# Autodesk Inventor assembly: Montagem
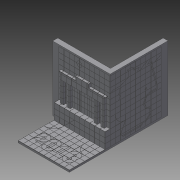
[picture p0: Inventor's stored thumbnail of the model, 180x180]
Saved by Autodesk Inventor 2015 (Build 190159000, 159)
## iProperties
Created: 2015-04
Part Number: Montagem
Document SubType Name: Assembly
Designer: Felipe
Author: Felipe
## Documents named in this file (65)
- F:\Visitor Experience Project\WSI2015 - Visitor Experience Project\#12- Wall and Floor Tiling\01 - 3D Models\Inventor Files\Montagem.iam
- C:\Users\TREINA5\Documents\Inventor\CNC Turning\Azulejo (1).ipt
- C:\Users\TREINA5\Documents\Inventor\CNC Turning\Azulejo (9).ipt
- C:\Users\TREINA5\Documents\Inventor\CNC Turning\Azulejo (10).ipt
- C:\Users\TREINA5\Documents\Inventor\CNC Turning\Azulejo (3).ipt
- C:\Users\TREINA5\Documents\Inventor\CNC Turning\Azulejo (2).ipt
- C:\Users\TREINA5\Documents\Inventor\CNC Turning\Azulejo (4).ipt
- C:\Users\TREINA5\Documents\Inventor\CNC Turning\Azulejo (5).ipt
- C:\Users\TREINA5\Documents\Inventor\CNC Turning\Azulejo (7).ipt
- C:\Users\TREINA5\Documents\Inventor\CNC Turning\Azulejo (6).ipt
- C:\Users\TREINA5\Documents\Inventor\CNC Turning\Azulejo (8).ipt
- F:\Visitor Experience Project\WSI2015 - Visitor Experience Project\#12- Wall and Floor Tiling\01 - 3D Models\Inventor Files\Azulejo (11).ipt
- F:\Visitor Experience Project\WSI2015 - Visitor Experience Project\#12- Wall and Floor Tiling\01 - 3D Models\Inventor Files\Azulejo (12).ipt
- F:\Visitor Experience Project\WSI2015 - Visitor Experience Project\#12- Wall and Floor Tiling\01 - 3D Models\Inventor Files\Azulejo (13).ipt
- F:\Visitor Experience Project\WSI2015 - Visitor Experience Project\#12- Wall and Floor Tiling\01 - 3D Models\Inventor Files\Azulejo (14).ipt
- F:\Visitor Experience Project\WSI2015 - Visitor Experience Project\#12- Wall and Floor Tiling\01 - 3D Models\Inventor Files\Azulejo (15).ipt
- F:\Visitor Experience Project\WSI2015 - Visitor Experience Project\#12- Wall and Floor Tiling\01 - 3D Models\Inventor Files\Azulejo (16).ipt
- F:\Visitor Experience Project\WSI2015 - Visitor Experience Project\#12- Wall and Floor Tiling\01 - 3D Models\Inventor Files\Azulejo (17).ipt
- F:\Visitor Experience Project\WSI2015 - Visitor Experience Project\#12- Wall and Floor Tiling\01 - 3D Models\Inventor Files\Azulejo (18).ipt
- F:\Visitor Experience Project\WSI2015 - Visitor Experience Project\#12- Wall and Floor Tiling\01 - 3D Models\Inventor Files\Azulejo (19).ipt
- F:\Visitor Experience Project\WSI2015 - Visitor Experience Project\#12- Wall and Floor Tiling\01 - 3D Models\Inventor Files\Azulejo (20).ipt
- F:\Visitor Experience Project\WSI2015 - Visitor Experience Project\#12- Wall and Floor Tiling\01 - 3D Models\Inventor Files\Azulejo (21).ipt
- F:\Visitor Experience Project\WSI2015 - Visitor Experience Project\#12- Wall and Floor Tiling\01 - 3D Models\Inventor Files\Azulejo (22).ipt
- F:\Visitor Experience Project\WSI2015 - Visitor Experience Project\#12- Wall and Floor Tiling\01 - 3D Models\Inventor Files\Azulejo (23).ipt
- F:\Visitor Experience Project\WSI2015 - Visitor Experience Project\#12- Wall and Floor Tiling\01 - 3D Models\Inventor Files\Azulejo (24).ipt
- F:\Visitor Experience Project\WSI2015 - Visitor Experience Project\#12- Wall and Floor Tiling\01 - 3D Models\Inventor Files\Azulejo (25).ipt
- F:\Visitor Experience Project\WSI2015 - Visitor Experience Project\#12- Wall and Floor Tiling\01 - 3D Models\Inventor Files\Azulejo (26).ipt
- F:\Visitor Experience Project\WSI2015 - Visitor Experience Project\#12- Wall and Floor Tiling\01 - 3D Models\Inventor Files\Azulejo (27).ipt
- F:\Visitor Experience Project\WSI2015 - Visitor Experience Project\#12- Wall and Floor Tiling\01 - 3D Models\Inventor Files\Azulejo (28).ipt
- F:\Visitor Experience Project\WSI2015 - Visitor Experience Project\#12- Wall and Floor Tiling\01 - 3D Models\Inventor Files\Azulejo (29).ipt
- F:\Visitor Experience Project\WSI2015 - Visitor Experience Project\#12- Wall and Floor Tiling\01 - 3D Models\Inventor Files\Azulejo (30).ipt
- F:\Visitor Experience Project\WSI2015 - Visitor Experience Project\#12- Wall and Floor Tiling\01 - 3D Models\Inventor Files\Azulejo (31).ipt
- F:\Visitor Experience Project\WSI2015 - Visitor Experience Project\#12- Wall and Floor Tiling\01 - 3D Models\Inventor Files\Azulejo (32).ipt
- F:\Visitor Experience Project\WSI2015 - Visitor Experience Project\#12- Wall and Floor Tiling\01 - 3D Models\Inventor Files\Azulejo (33).ipt
- F:\Visitor Experience Project\WSI2015 - Visitor Experience Project\#12- Wall and Floor Tiling\01 - 3D Models\Inventor Files\Azulejo (34).ipt
- F:\Visitor Experience Project\WSI2015 - Visitor Experience Project\#12- Wall and Floor Tiling\01 - 3D Models\Inventor Files\Azulejo (35).ipt
- F:\Visitor Experience Project\WSI2015 - Visitor Experience Project\#12- Wall and Floor Tiling\01 - 3D Models\Inventor Files\Azulejo (36).ipt
- F:\Visitor Experience Project\WSI2015 - Visitor Experience Project\#12- Wall and Floor Tiling\01 - 3D Models\Inventor Files\Azulejo (37).ipt
- F:\Visitor Experience Project\WSI2015 - Visitor Experience Project\#12- Wall and Floor Tiling\01 - 3D Models\Inventor Files\Azulejo (38).ipt
- F:\Visitor Experience Project\WSI2015 - Visitor Experience Project\#12- Wall and Floor Tiling\01 - 3D Models\Inventor Files\Azulejo (39).ipt
- F:\Visitor Experience Project\WSI2015 - Visitor Experience Project\#12- Wall and Floor Tiling\01 - 3D Models\Inventor Files\Azulejo (40).ipt
- F:\Visitor Experience Project\WSI2015 - Visitor Experience Project\#12- Wall and Floor Tiling\01 - 3D Models\Inventor Files\Azulejo (41).ipt
- F:\Visitor Experience Project\WSI2015 - Visitor Experience Project\#12- Wall and Floor Tiling\01 - 3D Models\Inventor Files\Azulejo (42).ipt
- F:\Visitor Experience Project\WSI2015 - Visitor Experience Project\#12- Wall and Floor Tiling\01 - 3D Models\Inventor Files\Azulejo (43).ipt
- F:\Visitor Experience Project\WSI2015 - Visitor Experience Project\#12- Wall and Floor Tiling\01 - 3D Models\Inventor Files\Azulejo (44).ipt
- F:\Visitor Experience Project\WSI2015 - Visitor Experience Project\#12- Wall and Floor Tiling\01 - 3D Models\Inventor Files\Azulejo (53).ipt
- F:\Visitor Experience Project\WSI2015 - Visitor Experience Project\#12- Wall and Floor Tiling\01 - 3D Models\Inventor Files\Azulejo (52).ipt
- F:\Visitor Experience Project\WSI2015 - Visitor Experience Project\#12- Wall and Floor Tiling\01 - 3D Models\Inventor Files\Azulejo (51).ipt
- F:\Visitor Experience Project\WSI2015 - Visitor Experience Project\#12- Wall and Floor Tiling\01 - 3D Models\Inventor Files\Azulejo (54).ipt
- F:\Visitor Experience Project\WSI2015 - Visitor Experience Project\#12- Wall and Floor Tiling\01 - 3D Models\Inventor Files\Azulejo (55).ipt
- F:\Visitor Experience Project\WSI2015 - Visitor Experience Project\#12- Wall and Floor Tiling\01 - 3D Models\Inventor Files\Azulejo (56).ipt
- F:\Visitor Experience Project\WSI2015 - Visitor Experience Project\#12- Wall and Floor Tiling\01 - 3D Models\Inventor Files\Azulejo (49).ipt
- F:\Visitor Experience Project\WSI2015 - Visitor Experience Project\#12- Wall and Floor Tiling\01 - 3D Models\Inventor Files\Azulejo (45).ipt
- F:\Visitor Experience Project\WSI2015 - Visitor Experience Project\#12- Wall and Floor Tiling\01 - 3D Models\Inventor Files\Azulejo (57).ipt
- F:\Visitor Experience Project\WSI2015 - Visitor Experience Project\#12- Wall and Floor Tiling\01 - 3D Models\Inventor Files\Azulejo (48).ipt
- F:\Visitor Experience Project\WSI2015 - Visitor Experience Project\#12- Wall and Floor Tiling\01 - 3D Models\Inventor Files\Azulejo (47).ipt
- F:\Visitor Experience Project\WSI2015 - Visitor Experience Project\#12- Wall and Floor Tiling\01 - 3D Models\Inventor Files\Azulejo (46).ipt
- F:\Visitor Experience Project\WSI2015 - Visitor Experience Project\#12- Wall and Floor Tiling\01 - 3D Models\Inventor Files\Azulejo (50).ipt
- F:\Visitor Experience Project\WSI2015 - Visitor Experience Project\#12- Wall and Floor Tiling\01 - 3D Models\Inventor Files\Azulejo (58).ipt
- F:\Visitor Experience Project\WSI2015 - Visitor Experience Project\#12- Wall and Floor Tiling\01 - 3D Models\Inventor Files\Azulejo (61).ipt
- F:\Visitor Experience Project\WSI2015 - Visitor Experience Project\#12- Wall and Floor Tiling\01 - 3D Models\Inventor Files\Azulejo (60).ipt
- F:\Visitor Experience Project\WSI2015 - Visitor Experience Project\#12- Wall and Floor Tiling\01 - 3D Models\Inventor Files\Azulejo (59).ipt
- F:\Visitor Experience Project\WSI2015 - Visitor Experience Project\#12- Wall and Floor Tiling\01 - 3D Models\Inventor Files\Azulejo (62).ipt
- F:\Visitor Experience Project\WSI2015 - Visitor Experience Project\#12- Wall and Floor Tiling\01 - 3D Models\Inventor Files\Azulejo (63).ipt
- F:\Visitor Experience Project\WSI2015 - Visitor Experience Project\#12- Wall and Floor Tiling\01 - 3D Models\Inventor Files\Parede.ipt
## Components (416 placed, 64 different names)
1. Parede:1 — Mate:1, Flush:1, Mate:2, Mate:3, Flush:2, Mate:5, Flush:3, Mate:7, Flush:4, Mate:9, Flush:5, Mate:11, Flush:6, Mate:13, Flush:7, Mate:15, Mate:17, Mate:19, Mate:21, Mate:23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
2. Azulejo (1):1 — Mate:1, Flush:1, Mate:2, Mate:4, Mate:47, Mate:197
3. Azulejo (1):2 — Mate:3, Flush:2, Mate:4, Mate:6, Mate:53
4. Azulejo (1):3 — Mate:5, Flush:3, Mate:6, Mate:8
5. Azulejo (1):4 — Mate:7, Flush:4, Mate:8, Mate:10
6. Azulejo (1):5 — Mate:9, Flush:5, Mate:10, Mate:12, Mate:155
7. Azulejo (1):6 — Mate:11, Flush:6, Mate:12, Mate:14
8. Azulejo (1):7 — Mate:15, Mate:16, Flush:8, Mate:18, Flush:9
9. Azulejo (1):8 — Mate:27, Mate:28, Flush:14, Mate:30, Flush:15, Mate:127, Mate:128
10. Azulejo (1):9 — Mate:29, Mate:30, Flush:15, Mate:32, Flush:16, Mate:124, Mate:125
11. Azulejo (1):10 — Mate:31, Mate:32, Flush:16, Mate:34, Flush:17
12. Azulejo (1):11 — Mate:37, Mate:38, Flush:19, Mate:40, Flush:20
13. Azulejo (1):12 — Mate:39, Mate:40, Flush:20, Flush:21
14. Azulejo (1):13 — Mate:48, Mate:49, Mate:50, Mate:55, Mate:78
15. Azulejo (1):14 — Mate:51, Mate:52, Mate:53, Mate:81
16. Azulejo (1):15 — Mate:33, Mate:34, Flush:17, Mate:36, Flush:18
17. Azulejo (1):16 — Mate:45, Mate:46, Mate:47, Mate:50, Mate:52
18. Azulejo (1):17 — Mate:54, Mate:55, Mate:56, Mate:59, Mate:96, Mate:97
19. Azulejo (1):20 — Mate:60, Mate:61, Mate:62, Mate:64, Mate:102, Mate:103
20. Azulejo (1):21 — Mate:13, Flush:7, Mate:14, Mate:16, Flush:8
21. Azulejo (1):22 — Mate:23, Mate:24, Flush:12, Mate:26, Flush:13
22. Azulejo (1):23 — Mate:21, Mate:22, Flush:11, Mate:24, Flush:12, Mate:182
23. Azulejo (1):24 — Mate:19, Mate:20, Flush:10, Mate:22, Flush:11, Mate:185
24. Azulejo (1):25 — Mate:17, Mate:18, Flush:9, Mate:20, Flush:10
25. Azulejo (1):26 — Mate:25, Mate:26, Flush:13, Mate:28, Flush:14
26. Azulejo (1):27 — Mate:35, Mate:36, Flush:18, Mate:38, Flush:19, Mate:130
27. Azulejo (1):30 — Mate:57, Mate:58, Mate:59, Mate:61, Mate:99, Mate:237
28. Azulejo (1):31 — Mate:66, Mate:67, Mate:68, Mate:94
29. Azulejo (1):32 — Mate:63, Mate:64, Mate:65, Mate:67, Mate:105, Mate:106
30. Azulejo (9):2 — Mate:72, Flush:21
31. Azulejo (10):1 — Mate:74, Mate:93
32. Azulejo (10):2 — Mate:83
33. Azulejo (9):3 — Mate:80, Mate:81
34. Azulejo (9):4 — Mate:77, Mate:78
35. Azulejo (9):5 — Mate:86, Mate:88
36. Azulejo (1):33 — Mate:89, Mate:90
37. Azulejo (1):34 — Mate:113, Mate:114, Mate:115
38. Azulejo (1):35 — Mate:101, Mate:102, Mate:103, Mate:114, Mate:115
39. Azulejo (1):36 — Mate:98, Mate:99, Mate:100, Mate:111, Mate:112
40. Azulejo (1):37 — Mate:92, Mate:93, Mate:94, Mate:120, Mate:121
41. Azulejo (1):38 — Mate:119, Mate:120, Mate:121, Mate:123, Flush:22
42. Azulejo (1):39 — Mate:110, Mate:111, Mate:112
43. Azulejo (1):40 — Mate:107, Mate:108, Mate:109
44. Azulejo (1):41 — Mate:95, Mate:96, Mate:97, Mate:100, Mate:108, Mate:109
45. Azulejo (1):44 — Mate:116, Mate:117, Mate:118
46. Azulejo (1):48 — Mate:122, Mate:123, Flush:22
47. Azulejo (1):49 — Mate:104, Mate:105, Mate:106, Mate:117, Mate:118
48. Azulejo (3):1 — Mate:124, Mate:125
49. Azulejo (2):1 — Mate:126, Mate:127, Mate:128
50. Azulejo (4):1 — Mate:129, Mate:130, Mate:137
51. Azulejo (5):1
52. Azulejo (5):2 — Mate:135, Mate:137
53. Azulejo (5):3 — Mate:138
54. Azulejo (5):4 — Mate:142
55. Azulejo (5):5 — Mate:143
56. Azulejo (5):6 — Mate:148
57. Azulejo (5):7 — Mate:149
58. Azulejo (7):1 — Mate:154, Mate:155
59. Azulejo (5):8 — Mate:157
60. Azulejo (5):9 — Mate:158
61. Azulejo (5):10 — Mate:163
62. Azulejo (5):11 — Mate:165
63. Azulejo (1):50 — Mate:169
64. Azulejo (2):2 — Mate:174
65. Azulejo (2):3 — Mate:172, Mate:189
66. Azulejo (6):1 — Mate:178
67. Azulejo (2):4 — Mate:193, Mate:194
68. Azulejo (2):5 — Mate:187, Mate:189
69. Azulejo (2):6 — Mate:190, Mate:194
70. Azulejo (8):1 — Mate:181, Mate:182, Mate:186
71. Azulejo (8):2 — Mate:184, Mate:185, Mate:186
72. Azulejo (1):51 — Mate:196, Mate:197, Flush:23, Flush:24, Mate:200, Mate:201, Mate:206, Mate:207, Mate:211, Mate:298
73. Azulejo (1):52 — Mate:198, Flush:24, Flush:42, Flush:45, Mate:288
74. Azulejo (1):53 — Mate:212, Mate:213, Mate:214, Mate:223, Mate:224, Mate:557, Flush:581, Mate:579
75. Azulejo (1):54 — Mate:202, Mate:203, Mate:204, Flush:26, Mate:213, Mate:214, Mate:555, Flush:572
76. Azulejo (1):55 — Mate:199, Mate:200, Mate:201, Mate:203, Mate:204, Flush:26, Mate:210, Flush:43, Mate:298
77. Azulejo (1):56 — Mate:215, Mate:216, Mate:217, Mate:219, Mate:226, Mate:227
78. Azulejo (1):57 — Mate:208, Mate:209, Mate:210, Mate:220, Mate:221, Mate:579
79. Azulejo (1):58 — Mate:205, Mate:206, Mate:207, Mate:209, Mate:211, Mate:216, Mate:217
80. Azulejo (1):59 — Mate:218, Mate:219, Mate:220, Mate:221, Mate:229, Mate:686
81. Azulejo (1):60 — Mate:228, Mate:229, Mate:230, Mate:239, Mate:240, Mate:580
82. Azulejo (1):61 — Mate:222, Mate:223, Mate:224, Mate:232, Mate:233, Mate:234, Mate:578, Mate:686
83. Azulejo (1):62 — Mate:235, Mate:236, Mate:237, Mate:244, Mate:245, Mate:581
84. Azulejo (1):63 — Mate:231, Mate:232, Mate:233, Mate:234, Mate:242, Flush:27, Flush:38, Mate:580, Mate:687
85. Azulejo (1):64 — Mate:225, Mate:226, Mate:227, Mate:230, Mate:236, Mate:687
86. Azulejo (1):65 — Mate:243, Mate:244, Mate:245, Mate:251, Flush:30
87. Azulejo (1):66 — Mate:241, Mate:242, Flush:27, Mate:249, Flush:29, Flush:39
88. Azulejo (1):67 — Mate:238, Mate:239, Mate:240, Mate:247, Flush:28, Mate:581
89. Azulejo (1):68 — Mate:248, Mate:249, Flush:29, Flush:40
90. Azulejo (1):69 — Mate:246, Mate:247, Flush:28, Mate:262
91. Azulejo (1):70 — Mate:250, Mate:251, Flush:30, Flush:570
92. Azulejo (1):73 — Mate:256, Flush:35, Flush:36, Flush:726, Mate:758
93. Azulejo (1):74 — Mate:259, Mate:269, Mate:270, Flush:36, Flush:644
94. Azulejo (1):75 — Mate:258, Mate:267, Mate:268, Mate:269, Mate:270, Flush:33, Mate:688, Mate:829
95. Azulejo (1):76 — Mate:257, Flush:33, Flush:34, Flush:35, Mate:569, Mate:570
96. Azulejo (1):77 — Mate:255, Mate:273, Flush:32, Flush:34, Flush:37, Mate:563, Mate:564
97. Azulejo (1):78 — Mate:254, Mate:262, Mate:267, Mate:268, Mate:273, Flush:32, Mate:275, Flush:569, Mate:551
98. Azulejo (1):79 — Mate:274, Flush:37, Mate:275, Flush:41, Flush:571
99. Azulejo (1):80 — Mate:278, Flush:39, Mate:279, Flush:777
100. Azulejo (1):81 — Mate:276, Flush:38, Mate:277, Flush:582, Flush:791
101. Azulejo (1):82 — Mate:280, Flush:40, Mate:281, Flush:785
102. Azulejo (1):83 — Mate:282, Flush:41, Mate:283, Flush:770
103. Azulejo (1):84 — Mate:285, Mate:286, Flush:44, Mate:294
104. Azulejo (1):85 — Mate:284, Flush:42, Flush:43, Mate:286, Flush:44, Mate:290
105. Azulejo (1):86 — Mate:287, Flush:45, Mate:288, Mate:291, Flush:47, Mate:299
106. Azulejo (1):87 — Mate:311, Flush:52, Mate:312, Mate:314, Flush:53, Mate:321, Mate:340, Mate:426
107. Azulejo (1):88 — Mate:307, Flush:50, Mate:308, Mate:310, Flush:51, Mate:341
108. Azulejo (1):89 — Mate:300, Flush:48, Mate:301, Mate:303, Mate:423
109. Azulejo (1):90 — Mate:309, Mate:310, Flush:51, Flush:52, Mate:312, Mate:321, Mate:340
110. Azulejo (1):91 — Mate:313, Mate:314, Flush:53, Flush:78, Mate:524
111. Azulejo (1):92 — Mate:302, Mate:303, Mate:304, Mate:317, Mate:423, Mate:518
112. Azulejo (1):93 — Mate:305, Mate:306, Flush:49, Flush:50, Mate:308, Mate:316, Mate:341
113. Azulejo (1):94 — Mate:295, Mate:296, Flush:46, Mate:306, Flush:49, Flush:536, Mate:530
114. Azulejo (1):95 — Mate:297, Flush:47, Mate:299, Mate:301
115. Azulejo (1):96 — Mate:292, Mate:293, Mate:294, Mate:296, Flush:46, Mate:304
116. Azulejo (1):97 — Mate:289, Mate:290, Mate:291, Mate:293, Flush:48
117. Azulejo (1):98 — Mate:329, Mate:330, Mate:331, Mate:335, Flush:57, Mate:339, Mate:400, Mate:401
118. Azulejo (1):99 — Mate:326, Mate:327, Mate:328, Mate:330, Mate:333, Flush:56, Mate:336, Mate:339, Mate:350
119. Azulejo (1):100 — Mate:324, Flush:55, Mate:325, Mate:331, Mate:384, Flush:66
120. Azulejo (1):101 — Mate:322, Mate:323, Flush:54, Mate:325, Mate:327, Mate:328, Mate:336, Flush:63
121. Azulejo (1):102 — Mate:318, Mate:319, Mate:320, Flush:55, Mate:425
122. Azulejo (1):103 — Mate:315, Mate:316, Mate:317, Mate:319, Mate:320, Mate:323, Flush:54
123. Azulejo (1):104 — Mate:334, Mate:335, Flush:57, Mate:343, Flush:59
124. Azulejo (1):105 — Mate:351, Flush:62, Flush:63, Mate:422, Mate:519, Flush:535, Mate:527, Mate:533
125. Azulejo (1):106 — Mate:348, Mate:349, Mate:350, Flush:62, Flush:65
126. Azulejo (1):107 — Mate:342, Mate:343, Flush:59, Mate:403, Mate:404, Mate:485
127. Azulejo (1):108 — Mate:337, Mate:338, Flush:58, Mate:345, Mate:346
128. Azulejo (1):109 — Mate:332, Mate:333, Flush:56, Mate:338, Flush:58, Flush:61
129. Azulejo (1):110 — Mate:390, Mate:408, Flush:69, Mate:409, Flush:70, Mate:428, Mate:438
130. Azulejo (1):111 — Mate:391, Mate:409, Flush:70, Mate:410, Flush:71, Flush:79
131. Azulejo (1):112 — Mate:354, Flush:64, Flush:65, Mate:368, Mate:369, Mate:422, Mate:495, Mate:499
132. Azulejo (1):113 — Mate:353, Mate:363, Mate:364, Flush:64, Mate:495, Mate:497
133. Azulejo (1):114 — Mate:352, Mate:361, Mate:362, Mate:363, Mate:365, Mate:366, Mate:509
134. Azulejo (1):115 — Mate:344, Mate:345, Mate:346, Flush:60, Mate:361, Mate:362, Mate:507
135. Azulejo (1):116 — Mate:397, Flush:76, Flush:77, Mate:421, Flush:89
136. Azulejo (1):117 — Mate:396, Mate:414, Mate:415, Mate:419, Mate:420, Mate:476
137. Azulejo (1):118 — Mate:360, Mate:371, Mate:372, Mate:374, Mate:516, Mate:549
138. Azulejo (1):119 — Mate:357, Mate:369, Mate:370, Mate:371, Mate:372, Mate:498, Mate:499, Flush:533
139. Azulejo (1):120 — Mate:356, Mate:367, Mate:368, Mate:370, Mate:373, Mate:496, Mate:497, Mate:498
140. Azulejo (1):121 — Mate:347, Flush:60, Flush:61, Mate:349, Mate:364
141. Azulejo (1):122 — Mate:378, Mate:379, Mate:380, Mate:381, Mate:382, Mate:887
142. Azulejo (1):123 — Mate:398, Flush:74, Flush:75, Flush:77, Mate:464
143. Azulejo (1):124 — Mate:377, Mate:381, Mate:382, Flush:518, Flush:523
144. Azulejo (1):125 — Mate:359, Mate:373, Mate:374, Mate:376, Mate:500, Flush:528
145. Azulejo (1):126 — Mate:358, Mate:375, Mate:376, Mate:500, Mate:515
146. Azulejo (1):127 — Mate:355, Mate:365, Mate:366, Mate:367, Mate:375, Mate:379, Mate:380, Mate:496
147. Azulejo (1):128 — Mate:389, Mate:407, Flush:68, Mate:414, Mate:419, Mate:479, Flush:102
148. Azulejo (1):129 — Mate:383, Mate:384, Flush:66, Mate:408, Flush:69
149. Azulejo (1):130 — Mate:388, Mate:406, Flush:67, Mate:407, Flush:68, Flush:103
150. Azulejo (1):131 — Mate:387, Mate:404, Mate:405, Mate:406, Flush:67
151. Azulejo (1):132 — Mate:386, Mate:402, Mate:403, Mate:405
152. Azulejo (1):133 — Mate:385, Mate:400, Mate:401, Mate:402
153. Azulejo (1):134 — Mate:399, Mate:416, Mate:417, Flush:75, Mate:431, Flush:87, Mate:460
154. Azulejo (1):136 — Mate:393, Mate:411, Flush:72, Mate:412, Flush:73, Flush:74
155. Azulejo (1):137 — Mate:394, Mate:412, Flush:73, Mate:415, Flush:76
156. Azulejo (1):138 — Mate:392, Mate:410, Flush:71, Mate:411, Flush:72, Mate:416, Mate:417
157. Azulejo (1):140 — Mate:418, Mate:420, Mate:421, Flush:91, Mate:472
158. Azulejo (11):1 — Mate:424, Mate:425, Mate:426, Mate:429
159. Azulejo (12):1 — Mate:427, Mate:428, Mate:429, Mate:433, Mate:524
160. Azulejo (13):1 — Mate:430, Flush:78, Mate:431, Mate:434, Flush:81, Flush:591
161. Azulejo (14):1 — Mate:432, Mate:433, Mate:434, Mate:435, Mate:437, Mate:441, Mate:446
162. Azulejo (15):1 — Mate:436, Mate:437, Mate:438, Flush:80, Mate:448
163. Azulejo (16):1 — Mate:439, Flush:79, Flush:80, Mate:453
164. Azulejo (1):141 — Mate:440, Flush:81, Mate:441, Flush:82, Mate:443, Mate:445, Flush:593
165. Azulejo (1):142 — Mate:442, Flush:82, Mate:443, Flush:84, Flush:594
166. Azulejo (1):143 — Mate:444, Mate:445, Mate:446, Mate:449, Flush:83
167. Azulejo (1):144 — Mate:451, Flush:85, Flush:86
168. Azulejo (1):145 — Mate:450, Flush:83, Flush:84, Flush:86
169. Azulejo (1):146 — Mate:447, Mate:448, Mate:449, Flush:85
170. Azulejo (17):1 — Mate:452, Mate:453, Mate:456, Mate:457
171. Azulejo (18):1 — Mate:455, Mate:456, Mate:457, Flush:88
172. Azulejo (19):1 — Mate:458, Flush:87, Flush:88, Mate:461, Flush:94
173. Azulejo (20):1 — Mate:459, Mate:460, Mate:461, Mate:471
174. Azulejo (21):1 — Mate:462, Mate:464, Flush:90, Flush:93, Mate:471
175. Azulejo (22):1 — Mate:465, Flush:89, Flush:90, Flush:92, Flush:96
176. Azulejo (1):147 — Mate:467, Flush:93, Flush:94, Flush:95
177. Azulejo (1):148 — Mate:468, Flush:95, Flush:96, Flush:98
178. Azulejo (1):149 — Mate:469, Flush:97, Flush:98, Mate:473, Flush:538
179. Azulejo (23):1 — Mate:466, Flush:91, Flush:92, Flush:97
180. Azulejo (24):1 — Mate:470, Mate:472, Mate:473, Flush:99, Mate:474, Flush:100, Mate:477, Flush:539
181. Azulejo (25):2 — Flush:99, Mate:474, Flush:100, Flush:541, Flush:543
182. Azulejo (26):1 — Mate:475, Mate:476, Mate:477, Mate:480, Flush:542
183. Azulejo (27):1 — Mate:478, Mate:479, Mate:480, Mate:482, Mate:483, Flush:544
184. Azulejo (28):1 — Mate:481, Mate:482, Mate:483, Flush:101, Flush:546
185. Azulejo (29):1 — Mate:484, Flush:101, Mate:485, Mate:488, Flush:104, Mate:491, Flush:106
186. Azulejo (30):1 — Mate:489, Flush:103, Mate:490, Mate:506
187. Azulejo (31):1 — Mate:487, Flush:102, Mate:488, Mate:490, Flush:108
188. Azulejo (32):1 — Flush:104, Mate:491, Flush:105, Mate:493
189. Azulejo (33):1 — Flush:105, Mate:493, Mate:502, Flush:551
190. Azulejo (34):1 — Mate:501, Flush:106, Mate:502, Flush:107, Mate:503, Flush:549
191. Azulejo (35):1 — Flush:107, Flush:108, Mate:503, Mate:505, Flush:508, Mate:508
192. Azulejo (36):1 — Flush:509, Flush:510, Flush:511, Flush:512, Mate:510
193. Azulejo (37):1 — Flush:508, Mate:507, Mate:508, Flush:509, Flush:511, Flush:513, Flush:548
194. Azulejo (38):1 — Flush:514, Flush:515, Mate:513, Flush:516, Flush:517, Flush:556, Flush:558, Mate:887
195. Azulejo (39):1 — Flush:516, Flush:517, Flush:518, Flush:519, Flush:520, Mate:514, Flush:560
196. Azulejo (40):1 — Flush:519, Flush:520, Mate:514, Flush:521, Flush:522, Flush:564, Flush:566
197. Azulejo (41):1 — Flush:521, Flush:522, Flush:523, Flush:524, Flush:525
198. Azulejo (42):1 — Flush:524, Flush:525, Mate:515, Flush:526, Flush:527
199. Azulejo (43):1 — Flush:531, Flush:532, Mate:517
200. Azulejo (44):1 — Flush:568, Mate:549, Mate:550
201. Azulejo (1):150 — Mate:504, Mate:505, Mate:506, Flush:510
202. Azulejo (36):2 — Flush:512, Mate:509, Mate:510, Mate:512, Mate:513
203. Azulejo (37):2 — Mate:511, Flush:513, Mate:512, Flush:514, Flush:515, Flush:552
204. Azulejo (42):2 — Flush:526, Flush:527, Flush:528, Flush:529, Flush:530
205. Azulejo (42):3 — Flush:529, Flush:530, Mate:516, Flush:531, Flush:532, Mate:517
206. Azulejo (44):2 — Flush:533, Mate:518, Mate:519, Flush:568, Mate:550
207. Azulejo (10):3 — Flush:536, Mate:530
208. Azulejo (9):6 — Mate:533
209. Azulejo (9):7 — Flush:535, Mate:527
210. Azulejo (1):151 — Mate:534, Flush:538, Flush:539, Flush:540
211. Azulejo (1):152 — Mate:535, Flush:540, Flush:541
212. Azulejo (1):153 — Mate:536, Flush:542, Flush:543, Flush:545
213. Azulejo (1):154 — Mate:537, Flush:544, Flush:545, Flush:547
214. Azulejo (1):155 — Mate:538, Flush:546, Flush:547
215. Azulejo (1):156 — Mate:539, Flush:548, Flush:549, Flush:550, Flush:553
216. Azulejo (1):157 — Mate:541, Flush:552, Flush:553, Flush:555, Flush:559
217. Azulejo (1):158 — Mate:543, Flush:558, Flush:559, Flush:561
218. Azulejo (1):159 — Mate:545, Flush:560, Flush:561, Flush:562, Flush:567
219. Azulejo (1):160 — Mate:547, Flush:566, Flush:567
220. Azulejo (1):161 — Mate:548, Flush:564, Flush:565
221. Azulejo (1):162 — Mate:546, Flush:562, Flush:563, Flush:565
222. Azulejo (1):163 — Mate:544, Flush:556, Flush:557, Flush:563
223. Azulejo (1):164 — Mate:542, Flush:554, Flush:555, Flush:557
224. Azulejo (1):165 — Mate:540, Flush:550, Flush:551, Flush:554
225. Azulejo (6):2 — Flush:571
226. Azulejo (6):3 — Flush:569, Flush:570, Mate:551, Mate:688, Flush:810
227. Azulejo (53):1 — Mate:556, Mate:557, Mate:558, Flush:580, Flush:581, Mate:720
228. Azulejo (53):2 — Mate:554, Mate:555, Flush:572, Mate:558, Flush:573, Mate:574
229. Azulejo (52):1 — Flush:582, Mate:578, Mate:720, Flush:800
230. Azulejo (52):2 — Mate:562, Mate:563, Mate:564
231. Azulejo (53):3 — Mate:757, Flush:726, Mate:758
232. Azulejo (53):4 — Mate:568, Mate:569, Mate:570, Flush:589
233. Azulejo (54):1 — Mate:572, Mate:575, Flush:576, Flush:747
234. Azulejo (54):2 — Mate:571, Flush:574, Mate:575, Flush:575, Flush:576, Flush:744
235. Azulejo (55):1 — Mate:573, Flush:573, Mate:574, Flush:575, Flush:578, Flush:579, Flush:585, Mate:587
236. Azulejo (51):2 — Mate:576, Flush:577, Flush:578, Flush:584
237. Azulejo (55):2 — Mate:577, Flush:579, Flush:580, Mate:593, Mate:602, Flush:661
238. Azulejo (51):3 — Mate:583, Flush:583, Flush:584, Flush:669
239. Azulejo (55):3 — Mate:584, Flush:585, Flush:586, Mate:587, Mate:588, Mate:594, Flush:647
240. Azulejo (55):4 — Mate:585, Flush:586, Flush:587, Mate:588, Mate:589, Mate:597, Flush:649
241. Azulejo (55):5 — Mate:586, Flush:587, Mate:589, Mate:591, Flush:588, Mate:600, Flush:651, Flush:659
242. Azulejo (55):6 — Mate:590, Mate:591, Flush:588, Mate:630, Mate:635, Mate:636, Flush:653
243. Azulejo (55):7 — Mate:595, Mate:596, Mate:597, Mate:599, Mate:609, Flush:657, Flush:665
244. Azulejo (55):8 — Mate:592, Mate:593, Mate:594, Mate:596, Mate:607, Flush:655, Flush:663
245. Azulejo (55):9 — Mate:598, Mate:599, Mate:600, Mate:611
246. Azulejo (55):10 — Mate:604, Mate:608, Mate:609, Mate:610, Mate:626, Flush:680, Flush:688, Flush:706
247. Azulejo (55):11 — Mate:603, Mate:606, Mate:607, Mate:608, Flush:678, Flush:686, Flush:704
248. Azulejo (55):12 — Mate:601, Flush:589, Mate:602, Mate:606, Flush:676, Flush:684, Flush:702
249. Azulejo (55):13 — Mate:605, Mate:610, Mate:611, Mate:628
250. Azulejo (55):14 — Mate:827, Flush:808, Flush:809
251. Azulejo (55):15 — Flush:806, Flush:807, Flush:809
252. Azulejo (55):16 — Mate:618, Mate:626, Mate:627, Flush:696, Flush:806
253. Azulejo (55):17 — Mate:620, Mate:629, Mate:630, Mate:632, Mate:633, Flush:700
254. Azulejo (55):18 — Mate:619, Mate:627, Mate:628, Mate:629, Flush:682, Flush:690, Flush:698
255. Azulejo (56):1 — Mate:631, Mate:632, Mate:633, Mate:638, Flush:712
256. Azulejo (56):2 — Mate:634, Mate:635, Mate:636, Mate:646, Mate:662, Mate:669, Flush:710
257. Azulejo (49):1 — Mate:637, Mate:638, Mate:641, Mate:689, Flush:714, Flush:838
258. Azulejo (49):2 — Mate:640, Mate:641, Flush:645, Mate:859
259. Azulejo (49):3 — Mate:644, Mate:646, Mate:648, Mate:669, Flush:597, Mate:670, Mate:671, Flush:605, Flush:717, Flush:842
260. Azulejo (49):4 — Mate:645, Mate:648, Mate:670, Mate:671, Flush:605, Flush:606, Mate:702, Flush:718
261. Azulejo (1):166 — Mate:652, Flush:625, Flush:632, Flush:633
262. Azulejo (1):167 — Mate:655, Flush:626, Flush:633, Flush:634
263. Azulejo (1):168 — Mate:658, Flush:617, Flush:618, Flush:632, Flush:640
264. Azulejo (1):169 — Mate:657, Flush:628, Flush:629, Mate:691, Flush:635
265. Azulejo (1):170 — Mate:654, Flush:626, Flush:627, Flush:630, Mate:691, Flush:631
266. Azulejo (1):171 — Mate:651, Flush:624, Flush:625, Flush:631
267. Azulejo (1):172 — Mate:650, Flush:623, Flush:624
268. Azulejo (1):173 — Mate:653, Mate:684, Flush:622, Flush:623, Mate:689, Flush:627
269. Azulejo (1):174 — Mate:656, Mate:683, Flush:621, Mate:684, Flush:622, Flush:629
270. Azulejo (1):175 — Mate:661, Flush:594, Flush:595, Flush:601
271. Azulejo (1):176 — Mate:660, Flush:592, Flush:593, Flush:595, Flush:599
272. Azulejo (1):177 — Mate:659, Mate:662, Flush:591, Flush:592, Flush:596
273. Azulejo (1):178 — Mate:666, Flush:603, Flush:607, Flush:608, Flush:610
274. Azulejo (1):179 — Mate:665, Flush:598, Flush:599, Flush:600, Flush:603
275. Azulejo (1):180 — Mate:663, Flush:596, Flush:597, Flush:598, Flush:604
276. Azulejo (1):181 — Mate:664, Flush:604, Flush:606, Flush:607, Flush:612
277. Azulejo (1):182 — Mate:667, Flush:602, Flush:608, Flush:609, Mate:675
278. Azulejo (1):183 — Mate:668, Flush:600, Flush:601, Flush:602
279. Azulejo (1):184 — Mate:672, Flush:609, Mate:675, Flush:611, Flush:618
280. Azulejo (1):185 — Mate:673, Flush:610, Flush:611, Flush:613, Flush:616
281. Azulejo (1):186 — Mate:674, Flush:612, Flush:613, Flush:614, Mate:679, Mate:703
282. Azulejo (1):187 — Mate:676, Flush:614, Mate:679, Flush:615, Flush:619, Mate:680, Flush:840
283. Azulejo (1):188 — Mate:677, Flush:615, Flush:616, Flush:617, Flush:630
284. Azulejo (1):189 — Mate:678, Flush:619, Mate:680, Mate:682, Flush:620, Mate:695, Flush:839
285. Azulejo (1):190 — Mate:681, Mate:682, Flush:620, Mate:683, Flush:621, Flush:636, Mate:704
286. Azulejo (1):191 — Mate:698, Flush:644
287. Azulejo (1):192 — Mate:828, Flush:810, Mate:829
288. Azulejo (1):193 — Mate:690, Flush:628, Flush:634, Flush:638
289. Azulejo (45):1 — Mate:694, Flush:639, Mate:695
290. Azulejo (45):2 — Mate:693, Flush:637, Flush:638, Mate:697
291. Azulejo (45):3 — Mate:696, Mate:697, Flush:640
292. Azulejo (45):4 — Mate:692, Flush:635, Flush:636, Flush:637, Flush:639
293. Azulejo (57):1 — Mate:700, Flush:645, Mate:704
294. Azulejo (57):2 — Mate:701, Mate:702, Mate:703
295. Azulejo (51):4 — Mate:705, Flush:646, Flush:647, Flush:745
296. Azulejo (51):5 — Mate:706, Flush:648, Flush:649, Flush:749
297. Azulejo (51):6 — Mate:707, Flush:650, Flush:651, Flush:667, Flush:753
298. Azulejo (51):7 — Mate:708, Flush:652, Flush:653, Flush:756
299. Azulejo (51):8 — Mate:709, Flush:654, Flush:655
300. Azulejo (51):9 — Mate:710, Flush:656, Flush:657
301. Azulejo (51):10 — Mate:711, Flush:658, Flush:659
302. Azulejo (51):11 — Mate:712, Flush:660, Flush:661, Flush:758
303. Azulejo (51):12 — Mate:713, Flush:662, Flush:663, Flush:671, Flush:760, Flush:763
304. Azulejo (51):13 — Mate:714, Flush:664, Flush:665, Flush:673, Flush:765
305. Azulejo (51):14 — Mate:715, Flush:666, Flush:667
306. Azulejo (51):15 — Mate:718, Flush:672, Flush:673, Mate:721
307. Azulejo (51):16 — Mate:716, Flush:668, Flush:669
308. Azulejo (51):17 — Mate:717, Flush:670, Flush:671
309. Azulejo (51):18 — Mate:719, Flush:674, Mate:721
310. Azulejo (51):19 — Mate:729, Flush:689, Flush:690
311. Azulejo (51):20 — Mate:728, Flush:687, Flush:688
312. Azulejo (51):21 — Mate:727, Flush:685, Flush:686, Flush:816
313. Azulejo (51):22 — Mate:726, Flush:683, Flush:684
314. Azulejo (51):23 — Mate:730, Flush:691, Flush:808, Flush:812
315. Azulejo (51):24 — Mate:731, Flush:693, Flush:807
316. Azulejo (51):25 — Mate:732, Flush:695, Flush:696, Flush:820
317. Azulejo (51):26 — Mate:733, Flush:697, Flush:698, Flush:822
318. Azulejo (51):27 — Mate:725, Flush:681, Flush:682, Flush:708
319. Azulejo (51):28 — Mate:724, Flush:679, Flush:680, Flush:775
320. Azulejo (51):29 — Mate:723, Flush:677, Flush:678, Flush:773
321. Azulejo (51):30 — Mate:722, Flush:675, Flush:676, Flush:771
322. Azulejo (51):31 — Mate:734, Flush:699, Flush:700
323. Azulejo (51):32 — Mate:735, Flush:701, Flush:702, Flush:827
324. Azulejo (51):33 — Mate:736, Flush:703, Flush:704, Flush:830
325. Azulejo (51):34 — Mate:737, Flush:705, Flush:706, Flush:834
326. Azulejo (51):35 — Mate:738, Flush:707, Flush:708
327. Azulejo (48):1 — Mate:740, Flush:711, Flush:712, Flush:851, Flush:853, Flush:854
328. Azulejo (48):2 — Mate:739, Flush:709, Flush:710
329. Azulejo (47):2 — Mate:747, Flush:718, Flush:719, Flush:741, Flush:843
330. Azulejo (47):3 — Mate:748, Flush:716, Flush:717, Flush:742
331. Azulejo (47):5 — Mate:741, Flush:713, Flush:714, Flush:727, Mate:767
332. Azulejo (47):6 — Mate:742, Flush:715, Flush:728
333. Azulejo (46):1 — Mate:751, Flush:722, Flush:723, Mate:755, Flush:725, Flush:730, Mate:870
334. Azulejo (46):2 — Mate:750, Flush:720, Flush:721, Mate:754, Flush:724, Flush:739, Mate:867, Flush:846, Mate:868, Mate:869, Flush:849
335. Azulejo (1):194 — Mate:752, Mate:755, Flush:725, Flush:735, Mate:862
336. Azulejo (1):195 — Mate:753, Mate:754, Flush:724, Flush:738, Mate:863
337. Azulejo (1):196 — Mate:766, Flush:742, Flush:743
338. Azulejo (1):197 — Mate:764, Flush:737, Flush:739, Flush:740
339. Azulejo (1):198 — Mate:763, Flush:736, Flush:737, Flush:738
340. Azulejo (1):199 — Mate:760, Flush:728, Flush:729, Flush:732
341. Azulejo (1):200 — Mate:759, Flush:727, Mate:767, Flush:729, Mate:848
342. Azulejo (1):201 — Mate:761, Flush:730, Flush:732, Flush:734
343. Azulejo (1):202 — Mate:762, Flush:734, Flush:735, Flush:736
344. Azulejo (1):203 — Mate:765, Flush:740, Flush:741, Flush:743
345. Azulejo (54):3 — Mate:769, Flush:744, Flush:745, Flush:746, Flush:748
346. Azulejo (54):4 — Mate:770, Flush:746, Flush:747, Flush:750
347. Azulejo (54):5 — Mate:771, Flush:748, Flush:749, Flush:751, Flush:752
348. Azulejo (54):6 — Mate:772, Flush:750, Flush:751, Flush:754
349. Azulejo (54):7 — Mate:773, Flush:752, Flush:753, Mate:776, Flush:755
350. Azulejo (54):8 — Mate:774, Flush:754, Mate:776
351. Azulejo (54):9 — Mate:775, Flush:755, Flush:756
352. Azulejo (54):10 — Mate:777, Mate:779, Flush:759, Flush:762
353. Azulejo (54):11 — Mate:778, Flush:757, Mate:779, Flush:758, Flush:759, Flush:761
354. Azulejo (54):12 — Mate:780, Flush:760, Flush:761, Flush:763, Flush:764, Flush:766
355. Azulejo (54):13 — Mate:781, Flush:762, Flush:764, Flush:768
356. Azulejo (54):14 — Mate:783, Flush:768, Mate:787, Flush:769
357. Azulejo (54):15 — Mate:782, Flush:765, Flush:766, Flush:767, Mate:786, Mate:787
358. Azulejo (54):16 — Mate:784, Flush:767, Mate:786, Mate:788
359. Azulejo (54):17 — Mate:785, Flush:769, Mate:788
360. Azulejo (50):1 — Mate:789, Flush:770, Flush:771, Flush:772, Flush:778, Flush:784, Flush:794, Mate:822
361. Azulejo (50):2 — Mate:793, Flush:777, Flush:778, Flush:779, Flush:790
362. Azulejo (50):3 — Mate:799, Flush:790, Flush:791, Mate:810, Mate:811, Flush:801
363. Azulejo (50):4 — Mate:807, Mate:810, Mate:811, Mate:812, Flush:803
364. Azulejo (50):5 — Mate:801, Flush:792, Mate:812, Flush:793, Flush:805
365. Azulejo (50):6 — Mate:802, Flush:793, Mate:813, Mate:824
366. Azulejo (50):7 — Mate:794, Flush:779, Flush:780, Flush:781
367. Azulejo (50):8 — Mate:790, Flush:772, Flush:773, Flush:774, Flush:780, Flush:787, Flush:796
368. Azulejo (50):9 — Mate:791, Flush:774, Flush:775, Mate:797, Flush:776, Flush:782, Flush:788, Flush:798
369. Azulejo (50):10 — Mate:795, Flush:781, Flush:782, Mate:798, Flush:783, Flush:792
370. Azulejo (50):11 — Mate:804, Flush:786, Flush:787, Mate:808
371. Azulejo (50):12 — Mate:803, Flush:784, Flush:785, Flush:786
372. Azulejo (50):13 — Mate:806, Flush:788, Mate:808, Flush:789
373. Azulejo (50):14 — Mate:805, Flush:789, Mate:809
374. Azulejo (50):15 — Mate:796, Mate:798, Flush:783, Mate:809, Mate:813
375. Azulejo (50):16 — Mate:792, Mate:797, Flush:776, Mate:823
376. Azulejo (58):1 — Mate:821, Flush:799, Mate:823
377. Azulejo (58):2 — Mate:820, Flush:797, Flush:798, Flush:799
378. Azulejo (58):3 — Mate:819, Flush:795, Flush:796, Flush:797
379. Azulejo (58):4 — Mate:818, Flush:794, Mate:822, Flush:795
380. Azulejo (58):5 — Mate:814, Flush:800, Flush:801, Flush:802
381. Azulejo (58):6 — Mate:815, Flush:802, Flush:803, Flush:804
382. Azulejo (58):7 — Mate:816, Flush:804, Flush:805, Mate:825
383. Azulejo (58):8 — Mate:817, Mate:824, Mate:825
384. Azulejo (54):18 — Mate:837, Flush:835, Flush:836, Flush:841
385. Azulejo (54):19 — Mate:836, Flush:833, Flush:834, Flush:836, Flush:837, Mate:851
386. Azulejo (54):20 — Mate:835, Flush:831, Flush:832, Flush:835
387. Azulejo (54):21 — Mate:834, Flush:829, Flush:830, Flush:832, Flush:833
388. Azulejo (54):22 — Mate:833, Flush:828, Mate:850, Flush:831
389. Azulejo (54):23 — Mate:832, Flush:826, Flush:827, Flush:828, Mate:850, Flush:829
390. Azulejo (54):24 — Mate:830, Flush:837, Mate:851, Mate:852
391. Azulejo (54):25 — Mate:831, Mate:852, Flush:841
392. Azulejo (54):26 — Mate:838, Mate:847, Flush:814, Flush:817
393. Azulejo (54):27 — Mate:839, Flush:812, Flush:813, Mate:847, Flush:814, Flush:815
394. Azulejo (54):28 — Mate:841, Flush:815, Flush:818, Flush:819
395. Azulejo (54):29 — Mate:840, Flush:816, Flush:817, Flush:818
396. Azulejo (54):30 — Mate:842, Flush:824, Flush:825
397. Azulejo (54):31 — Mate:843, Flush:819, Flush:820, Flush:821, Flush:824
398. Azulejo (54):32 — Mate:845, Flush:821, Flush:822, Flush:823, Mate:849
399. Azulejo (54):33 — Mate:844, Flush:825, Mate:849
400. Azulejo (54):34 — Mate:846, Flush:823, Mate:848
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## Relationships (1215: Mate 768, Flush 447)
- Mate:1: Parede:1 ↔ Azulejo (1):1
- Flush:1: Parede:1 ↔ Azulejo (1):1
- Mate:2: Parede:1 ↔ Azulejo (1):1
- Mate:3: Parede:1 ↔ Azulejo (1):2
- Flush:2: Parede:1 ↔ Azulejo (1):2
- Mate:4: Azulejo (1):1 ↔ Azulejo (1):2
- Mate:5: Parede:1 ↔ Azulejo (1):3
- Flush:3: Parede:1 ↔ Azulejo (1):3
- Mate:6: Azulejo (1):2 ↔ Azulejo (1):3
- Mate:7: Parede:1 ↔ Azulejo (1):4
- Flush:4: Parede:1 ↔ Azulejo (1):4
- Mate:8: Azulejo (1):3 ↔ Azulejo (1):4
- Mate:9: Parede:1 ↔ Azulejo (1):5
- Flush:5: Parede:1 ↔ Azulejo (1):5
- Mate:10: Azulejo (1):4 ↔ Azulejo (1):5
- Mate:11: Parede:1 ↔ Azulejo (1):6
- Flush:6: Parede:1 ↔ Azulejo (1):6
- Mate:12: Azulejo (1):5 ↔ Azulejo (1):6
- Mate:13: Parede:1 ↔ Azulejo (1):21
- Flush:7: Parede:1 ↔ Azulejo (1):21
- Mate:14: Azulejo (1):6 ↔ Azulejo (1):21
- Mate:15: Parede:1 ↔ Azulejo (1):7
- Mate:16: Azulejo (1):7 ↔ Azulejo (1):21
- Flush:8: Azulejo (1):7 ↔ Azulejo (1):21
- Mate:17: Parede:1 ↔ Azulejo (1):25
- Mate:18: Azulejo (1):7 ↔ Azulejo (1):25
- Flush:9: Azulejo (1):7 ↔ Azulejo (1):25
- Mate:19: Parede:1 ↔ Azulejo (1):24
- Mate:20: Azulejo (1):24 ↔ Azulejo (1):25
- Flush:10: Azulejo (1):24 ↔ Azulejo (1):25
- Mate:21: Parede:1 ↔ Azulejo (1):23
- Mate:22: Azulejo (1):23 ↔ Azulejo (1):24
- Flush:11: Azulejo (1):23 ↔ Azulejo (1):24
- Mate:23: Parede:1 ↔ Azulejo (1):22
- Mate:24: Azulejo (1):22 ↔ Azulejo (1):23
- Flush:12: Azulejo (1):22 ↔ Azulejo (1):23
- Mate:25: Parede:1 ↔ Azulejo (1):26
- Mate:26: Azulejo (1):22 ↔ Azulejo (1):26
- Flush:13: Azulejo (1):22 ↔ Azulejo (1):26
- Mate:27: Parede:1 ↔ Azulejo (1):8
- Mate:28: Azulejo (1):8 ↔ Azulejo (1):26
- Flush:14: Azulejo (1):8 ↔ Azulejo (1):26
- Mate:29: Parede:1 ↔ Azulejo (1):9
- Mate:30: Azulejo (1):8 ↔ Azulejo (1):9
- Flush:15: Azulejo (1):8 ↔ Azulejo (1):9
- Mate:31: Parede:1 ↔ Azulejo (1):10
- Mate:32: Azulejo (1):9 ↔ Azulejo (1):10
- Flush:16: Azulejo (1):9 ↔ Azulejo (1):10
- Mate:33: Parede:1 ↔ Azulejo (1):15
- Mate:34: Azulejo (1):10 ↔ Azulejo (1):15
- Flush:17: Azulejo (1):10 ↔ Azulejo (1):15
- Mate:35: Parede:1 ↔ Azulejo (1):27
- Mate:36: Azulejo (1):15 ↔ Azulejo (1):27
- Flush:18: Azulejo (1):15 ↔ Azulejo (1):27
- Mate:37: Parede:1 ↔ Azulejo (1):11
- Mate:38: Azulejo (1):11 ↔ Azulejo (1):27
- Flush:19: Azulejo (1):11 ↔ Azulejo (1):27
- Mate:39: Parede:1 ↔ Azulejo (1):12
- Mate:40: Azulejo (1):11 ↔ Azulejo (1):12
- Flush:20: Azulejo (1):11 ↔ Azulejo (1):12
- Mate:45: Parede:1 ↔ Azulejo (1):16
- Mate:46: Parede:1 ↔ Azulejo (1):16
- Mate:47: Azulejo (1):1 ↔ Azulejo (1):16
- Mate:48: Parede:1 ↔ Azulejo (1):13
- Mate:49: Parede:1 ↔ Azulejo (1):13
- Mate:50: Azulejo (1):13 ↔ Azulejo (1):16
- Mate:51: Parede:1 ↔ Azulejo (1):14
- Mate:52: Azulejo (1):14 ↔ Azulejo (1):16
- Mate:53: Azulejo (1):2 ↔ Azulejo (1):14
- Mate:54: Parede:1 ↔ Azulejo (1):17
- Mate:55: Azulejo (1):13 ↔ Azulejo (1):17
- Mate:56: Parede:1 ↔ Azulejo (1):17
- Mate:57: Parede:1 ↔ Azulejo (1):30
- Mate:58: Parede:1 ↔ Azulejo (1):30
- Mate:59: Azulejo (1):17 ↔ Azulejo (1):30
- Mate:60: Parede:1 ↔ Azulejo (1):20
- Mate:61: Azulejo (1):20 ↔ Azulejo (1):30
- Mate:62: Parede:1 ↔ Azulejo (1):20
- Mate:63: Parede:1 ↔ Azulejo (1):32
- Mate:64: Azulejo (1):20 ↔ Azulejo (1):32
- Mate:65: Parede:1 ↔ Azulejo (1):32
- Mate:66: Parede:1 ↔ Azulejo (1):31
- Mate:67: Azulejo (1):31 ↔ Azulejo (1):32
- Mate:68: Parede:1 ↔ Azulejo (1):31
- Mate:72: Parede:1 ↔ Azulejo (9):2
- Flush:21: Azulejo (1):12 ↔ Azulejo (9):2
- Mate:74: Parede:1 ↔ Azulejo (10):1
- Mate:77: Parede:1 ↔ Azulejo (9):4
- Mate:78: Azulejo (1):13 ↔ Azulejo (9):4
- Mate:80: Parede:1 ↔ Azulejo (9):3
- Mate:81: Azulejo (1):14 ↔ Azulejo (9):3
- Mate:83: Parede:1 ↔ Azulejo (10):2
- Mate:86: Parede:1 ↔ Azulejo (9):5
- Mate:88: Parede:1 ↔ Azulejo (9):5
- Mate:89: Parede:1 ↔ Azulejo (1):33
- Mate:90: Parede:1 ↔ Azulejo (1):33
- Mate:92: Parede:1 ↔ Azulejo (1):37
- Mate:93: Azulejo (10):1 ↔ Azulejo (1):37
- Mate:94: Azulejo (1):31 ↔ Azulejo (1):37
- Mate:95: Parede:1 ↔ Azulejo (1):41
- Mate:96: Azulejo (1):17 ↔ Azulejo (1):41
- Mate:97: Azulejo (1):17 ↔ Azulejo (1):41
- Mate:98: Parede:1 ↔ Azulejo (1):36
- Mate:99: Azulejo (1):30 ↔ Azulejo (1):36
- Mate:100: Azulejo (1):36 ↔ Azulejo (1):41
- Mate:101: Parede:1 ↔ Azulejo (1):35
- Mate:102: Azulejo (1):20 ↔ Azulejo (1):35
- Mate:103: Azulejo (1):20 ↔ Azulejo (1):35
- Mate:104: Parede:1 ↔ Azulejo (1):49
- Mate:105: Azulejo (1):32 ↔ Azulejo (1):49
- Mate:106: Azulejo (1):32 ↔ Azulejo (1):49
- Mate:107: Parede:1 ↔ Azulejo (1):40
- Mate:108: Azulejo (1):40 ↔ Azulejo (1):41
- Mate:109: Azulejo (1):40 ↔ Azulejo (1):41
- Mate:110: Parede:1 ↔ Azulejo (1):39
- Mate:111: Azulejo (1):36 ↔ Azulejo (1):39
- Mate:112: Azulejo (1):36 ↔ Azulejo (1):39
- Mate:113: Parede:1 ↔ Azulejo (1):34
- Mate:114: Azulejo (1):34 ↔ Azulejo (1):35
- Mate:115: Azulejo (1):34 ↔ Azulejo (1):35
- Mate:116: Parede:1 ↔ Azulejo (1):44
- Mate:117: Azulejo (1):44 ↔ Azulejo (1):49
- Mate:118: Azulejo (1):44 ↔ Azulejo (1):49
- Mate:119: Parede:1 ↔ Azulejo (1):38
- Mate:120: Azulejo (1):37 ↔ Azulejo (1):38
- Mate:121: Azulejo (1):37 ↔ Azulejo (1):38
- Mate:122: Parede:1 ↔ Azulejo (1):48
- Mate:123: Azulejo (1):38 ↔ Azulejo (1):48
- Flush:22: Azulejo (1):38 ↔ Azulejo (1):48
- Mate:124: Azulejo (1):9 ↔ Azulejo (3):1
- Mate:125: Azulejo (1):9 ↔ Azulejo (3):1
- Mate:126: Parede:1 ↔ Azulejo (2):1
- Mate:127: Azulejo (1):8 ↔ Azulejo (2):1
- Mate:128: Azulejo (1):8 ↔ Azulejo (2):1
- Mate:129: Parede:1 ↔ Azulejo (4):1
- Mate:130: Azulejo (1):27 ↔ Azulejo (4):1
- Mate:135: Parede:1 ↔ Azulejo (5):2
- Mate:137: Azulejo (4):1 ↔ Azulejo (5):2
- Mate:138: Parede:1 ↔ Azulejo (5):3
- Mate:142: Parede:1 ↔ Azulejo (5):4
- Mate:143: Parede:1 ↔ Azulejo (5):5
- Mate:148: Parede:1 ↔ Azulejo (5):6
- Mate:149: Parede:1 ↔ Azulejo (5):7
- Mate:154: Parede:1 ↔ Azulejo (7):1
- Mate:155: Azulejo (1):5 ↔ Azulejo (7):1
- Mate:157: Parede:1 ↔ Azulejo (5):8
- Mate:158: Parede:1 ↔ Azulejo (5):9
- Mate:163: Parede:1 ↔ Azulejo (5):10
- Mate:165: Parede:1 ↔ Azulejo (5):11
- Mate:169: Parede:1 ↔ Azulejo (1):50
- Mate:172: Parede:1 ↔ Azulejo (2):3
- Mate:174: Parede:1 ↔ Azulejo (2):2
- Mate:178: Parede:1 ↔ Azulejo (6):1
- Mate:181: Parede:1 ↔ Azulejo (8):1
- Mate:182: Azulejo (1):23 ↔ Azulejo (8):1
- Mate:184: Parede:1 ↔ Azulejo (8):2
- Mate:185: Azulejo (1):24 ↔ Azulejo (8):2
- Mate:186: Azulejo (8):1 ↔ Azulejo (8):2
- Mate:187: Parede:1 ↔ Azulejo (2):5
- Mate:189: Azulejo (2):3 ↔ Azulejo (2):5
- Mate:190: Parede:1 ↔ Azulejo (2):6
- Mate:193: Parede:1 ↔ Azulejo (2):4
- Mate:194: Azulejo (2):4 ↔ Azulejo (2):6
- Mate:196: Parede:1 ↔ Azulejo (1):51
- Mate:197: Azulejo (1):1 ↔ Azulejo (1):51
- Flush:23: Parede:1 ↔ Azulejo (1):51
- Mate:198: Parede:1 ↔ Azulejo (1):52
- Flush:24: Azulejo (1):51 ↔ Azulejo (1):52
- Mate:199: Parede:1 ↔ Azulejo (1):55
- Mate:200: Azulejo (1):51 ↔ Azulejo (1):55
- Mate:201: Azulejo (1):51 ↔ Azulejo (1):55
- Mate:202: Parede:1 ↔ Azulejo (1):54
- Mate:203: Azulejo (1):54 ↔ Azulejo (1):55
- Mate:204: Azulejo (1):54 ↔ Azulejo (1):55
- Flush:26: Azulejo (1):54 ↔ Azulejo (1):55
- Mate:205: Parede:1 ↔ Azulejo (1):58
- Mate:206: Azulejo (1):51 ↔ Azulejo (1):58
- Mate:207: Azulejo (1):51 ↔ Azulejo (1):58
- Mate:208: Parede:1 ↔ Azulejo (1):57
- Mate:209: Azulejo (1):57 ↔ Azulejo (1):58
- Mate:210: Azulejo (1):55 ↔ Azulejo (1):57
- Mate:211: Azulejo (1):51 ↔ Azulejo (1):58
- Mate:212: Parede:1 ↔ Azulejo (1):53
- Mate:213: Azulejo (1):53 ↔ Azulejo (1):54
- Mate:214: Azulejo (1):53 ↔ Azulejo (1):54
- Mate:215: Parede:1 ↔ Azulejo (1):56
- Mate:216: Azulejo (1):56 ↔ Azulejo (1):58
- Mate:217: Azulejo (1):56 ↔ Azulejo (1):58
- Mate:218: Parede:1 ↔ Azulejo (1):59
- Mate:219: Azulejo (1):56 ↔ Azulejo (1):59
- Mate:220: Azulejo (1):57 ↔ Azulejo (1):59
- Mate:221: Azulejo (1):57 ↔ Azulejo (1):59
- Mate:222: Parede:1 ↔ Azulejo (1):61
- Mate:223: Azulejo (1):53 ↔ Azulejo (1):61
- Mate:224: Azulejo (1):53 ↔ Azulejo (1):61
- Mate:225: Parede:1 ↔ Azulejo (1):64
- Mate:226: Azulejo (1):56 ↔ Azulejo (1):64
- Mate:227: Azulejo (1):56 ↔ Azulejo (1):64
- Mate:228: Parede:1 ↔ Azulejo (1):60
- Mate:229: Azulejo (1):59 ↔ Azulejo (1):60
- Mate:230: Azulejo (1):60 ↔ Azulejo (1):64
- Mate:231: Parede:1 ↔ Azulejo (1):63
- Mate:232: Azulejo (1):61 ↔ Azulejo (1):63
- Mate:233: Azulejo (1):61 ↔ Azulejo (1):63
- Mate:234: Azulejo (1):61 ↔ Azulejo (1):63
- Mate:235: Parede:1 ↔ Azulejo (1):62
- Mate:236: Azulejo (1):62 ↔ Azulejo (1):64
- Mate:237: Azulejo (1):30 ↔ Azulejo (1):62
- Mate:238: Parede:1 ↔ Azulejo (1):67
- Mate:239: Azulejo (1):60 ↔ Azulejo (1):67
- Mate:240: Azulejo (1):60 ↔ Azulejo (1):67
- Mate:241: Parede:1 ↔ Azulejo (1):66
- Mate:242: Azulejo (1):63 ↔ Azulejo (1):66
- Flush:27: Azulejo (1):63 ↔ Azulejo (1):66
- Mate:243: Parede:1 ↔ Azulejo (1):65
- Mate:244: Azulejo (1):62 ↔ Azulejo (1):65
- Mate:245: Azulejo (1):62 ↔ Azulejo (1):65
- Mate:246: Parede:1 ↔ Azulejo (1):69
- Mate:247: Azulejo (1):67 ↔ Azulejo (1):69
- Flush:28: Azulejo (1):67 ↔ Azulejo (1):69
- Mate:248: Parede:1 ↔ Azulejo (1):68
- Mate:249: Azulejo (1):66 ↔ Azulejo (1):68
- Flush:29: Azulejo (1):66 ↔ Azulejo (1):68
- Mate:250: Parede:1 ↔ Azulejo (1):70
- Mate:251: Azulejo (1):65 ↔ Azulejo (1):70
- Flush:30: Azulejo (1):65 ↔ Azulejo (1):70
- Mate:254: Parede:1 ↔ Azulejo (1):78
- Mate:255: Parede:1 ↔ Azulejo (1):77
- Mate:256: Parede:1 ↔ Azulejo (1):73
- Mate:257: Parede:1 ↔ Azulejo (1):76
- Mate:258: Parede:1 ↔ Azulejo (1):75
- Mate:259: Parede:1 ↔ Azulejo (1):74
- Mate:262: Azulejo (1):69 ↔ Azulejo (1):78
- Mate:267: Azulejo (1):75 ↔ Azulejo (1):78
- Mate:268: Azulejo (1):75 ↔ Azulejo (1):78
- Mate:269: Azulejo (1):74 ↔ Azulejo (1):75
- Mate:270: Azulejo (1):74 ↔ Azulejo (1):75
- Mate:273: Azulejo (1):77 ↔ Azulejo (1):78
- Flush:32: Azulejo (1):77 ↔ Azulejo (1):78
- Flush:33: Azulejo (1):75 ↔ Azulejo (1):76
- Flush:34: Azulejo (1):76 ↔ Azulejo (1):77
- Flush:35: Azulejo (1):73 ↔ Azulejo (1):76
- Flush:36: Azulejo (1):73 ↔ Azulejo (1):74
- Mate:274: Parede:1 ↔ Azulejo (1):79
- Flush:37: Azulejo (1):77 ↔ Azulejo (1):79
- Mate:275: Azulejo (1):78 ↔ Azulejo (1):79
- Mate:276: Parede:1 ↔ Azulejo (1):81
- Flush:38: Azulejo (1):63 ↔ Azulejo (1):81
- Mate:277: Parede:1 ↔ Azulejo (1):81
- Mate:278: Parede:1 ↔ Azulejo (1):80
- Flush:39: Azulejo (1):66 ↔ Azulejo (1):80
- Mate:279: Parede:1 ↔ Azulejo (1):80
- Mate:280: Parede:1 ↔ Azulejo (1):82
- Flush:40: Azulejo (1):68 ↔ Azulejo (1):82
- Mate:281: Parede:1 ↔ Azulejo (1):82
- Mate:282: Parede:1 ↔ Azulejo (1):83
- Flush:41: Azulejo (1):79 ↔ Azulejo (1):83
- Mate:283: Parede:1 ↔ Azulejo (1):83
- Mate:284: Parede:1 ↔ Azulejo (1):85
- Flush:42: Azulejo (1):52 ↔ Azulejo (1):85
- Flush:43: Azulejo (1):55 ↔ Azulejo (1):85
- Mate:285: Parede:1 ↔ Azulejo (1):84
- Mate:286: Azulejo (1):84 ↔ Azulejo (1):85
- Flush:44: Azulejo (1):84 ↔ Azulejo (1):85
- Mate:287: Parede:1 ↔ Azulejo (1):86
- Flush:45: Azulejo (1):52 ↔ Azulejo (1):86
- Mate:288: Azulejo (1):52 ↔ Azulejo (1):86
- Mate:289: Parede:1 ↔ Azulejo (1):97
- Mate:290: Azulejo (1):85 ↔ Azulejo (1):97
- Mate:291: Azulejo (1):86 ↔ Azulejo (1):97
- Mate:292: Parede:1 ↔ Azulejo (1):96
- Mate:293: Azulejo (1):96 ↔ Azulejo (1):97
- Mate:294: Azulejo (1):84 ↔ Azulejo (1):96
- Mate:295: Parede:1 ↔ Azulejo (1):94
- Mate:296: Azulejo (1):94 ↔ Azulejo (1):96
- Flush:46: Azulejo (1):94 ↔ Azulejo (1):96
- Mate:297: Parede:1 ↔ Azulejo (1):95
- Mate:298: Azulejo (1):51 ↔ Azulejo (1):55
- Flush:47: Azulejo (1):86 ↔ Azulejo (1):95
- Mate:299: Azulejo (1):86 ↔ Azulejo (1):95
- Mate:300: Parede:1 ↔ Azulejo (1):89
- Flush:48: Azulejo (1):89 ↔ Azulejo (1):97
- Mate:301: Azulejo (1):89 ↔ Azulejo (1):95
- Mate:302: Parede:1 ↔ Azulejo (1):92
- Mate:303: Azulejo (1):89 ↔ Azulejo (1):92
- Mate:304: Azulejo (1):92 ↔ Azulejo (1):96
- Mate:305: Parede:1 ↔ Azulejo (1):93
- Mate:306: Azulejo (1):93 ↔ Azulejo (1):94
- Flush:49: Azulejo (1):93 ↔ Azulejo (1):94
- Mate:307: Parede:1 ↔ Azulejo (1):88
- Flush:50: Azulejo (1):88 ↔ Azulejo (1):93
- Mate:308: Azulejo (1):88 ↔ Azulejo (1):93
- Mate:309: Parede:1 ↔ Azulejo (1):90
- Mate:310: Azulejo (1):88 ↔ Azulejo (1):90
- Flush:51: Azulejo (1):88 ↔ Azulejo (1):90
- Mate:311: Parede:1 ↔ Azulejo (1):87
- Flush:52: Azulejo (1):87 ↔ Azulejo (1):90
- Mate:312: Azulejo (1):87 ↔ Azulejo (1):90
- Mate:313: Parede:1 ↔ Azulejo (1):91
- Mate:314: Azulejo (1):87 ↔ Azulejo (1):91
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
